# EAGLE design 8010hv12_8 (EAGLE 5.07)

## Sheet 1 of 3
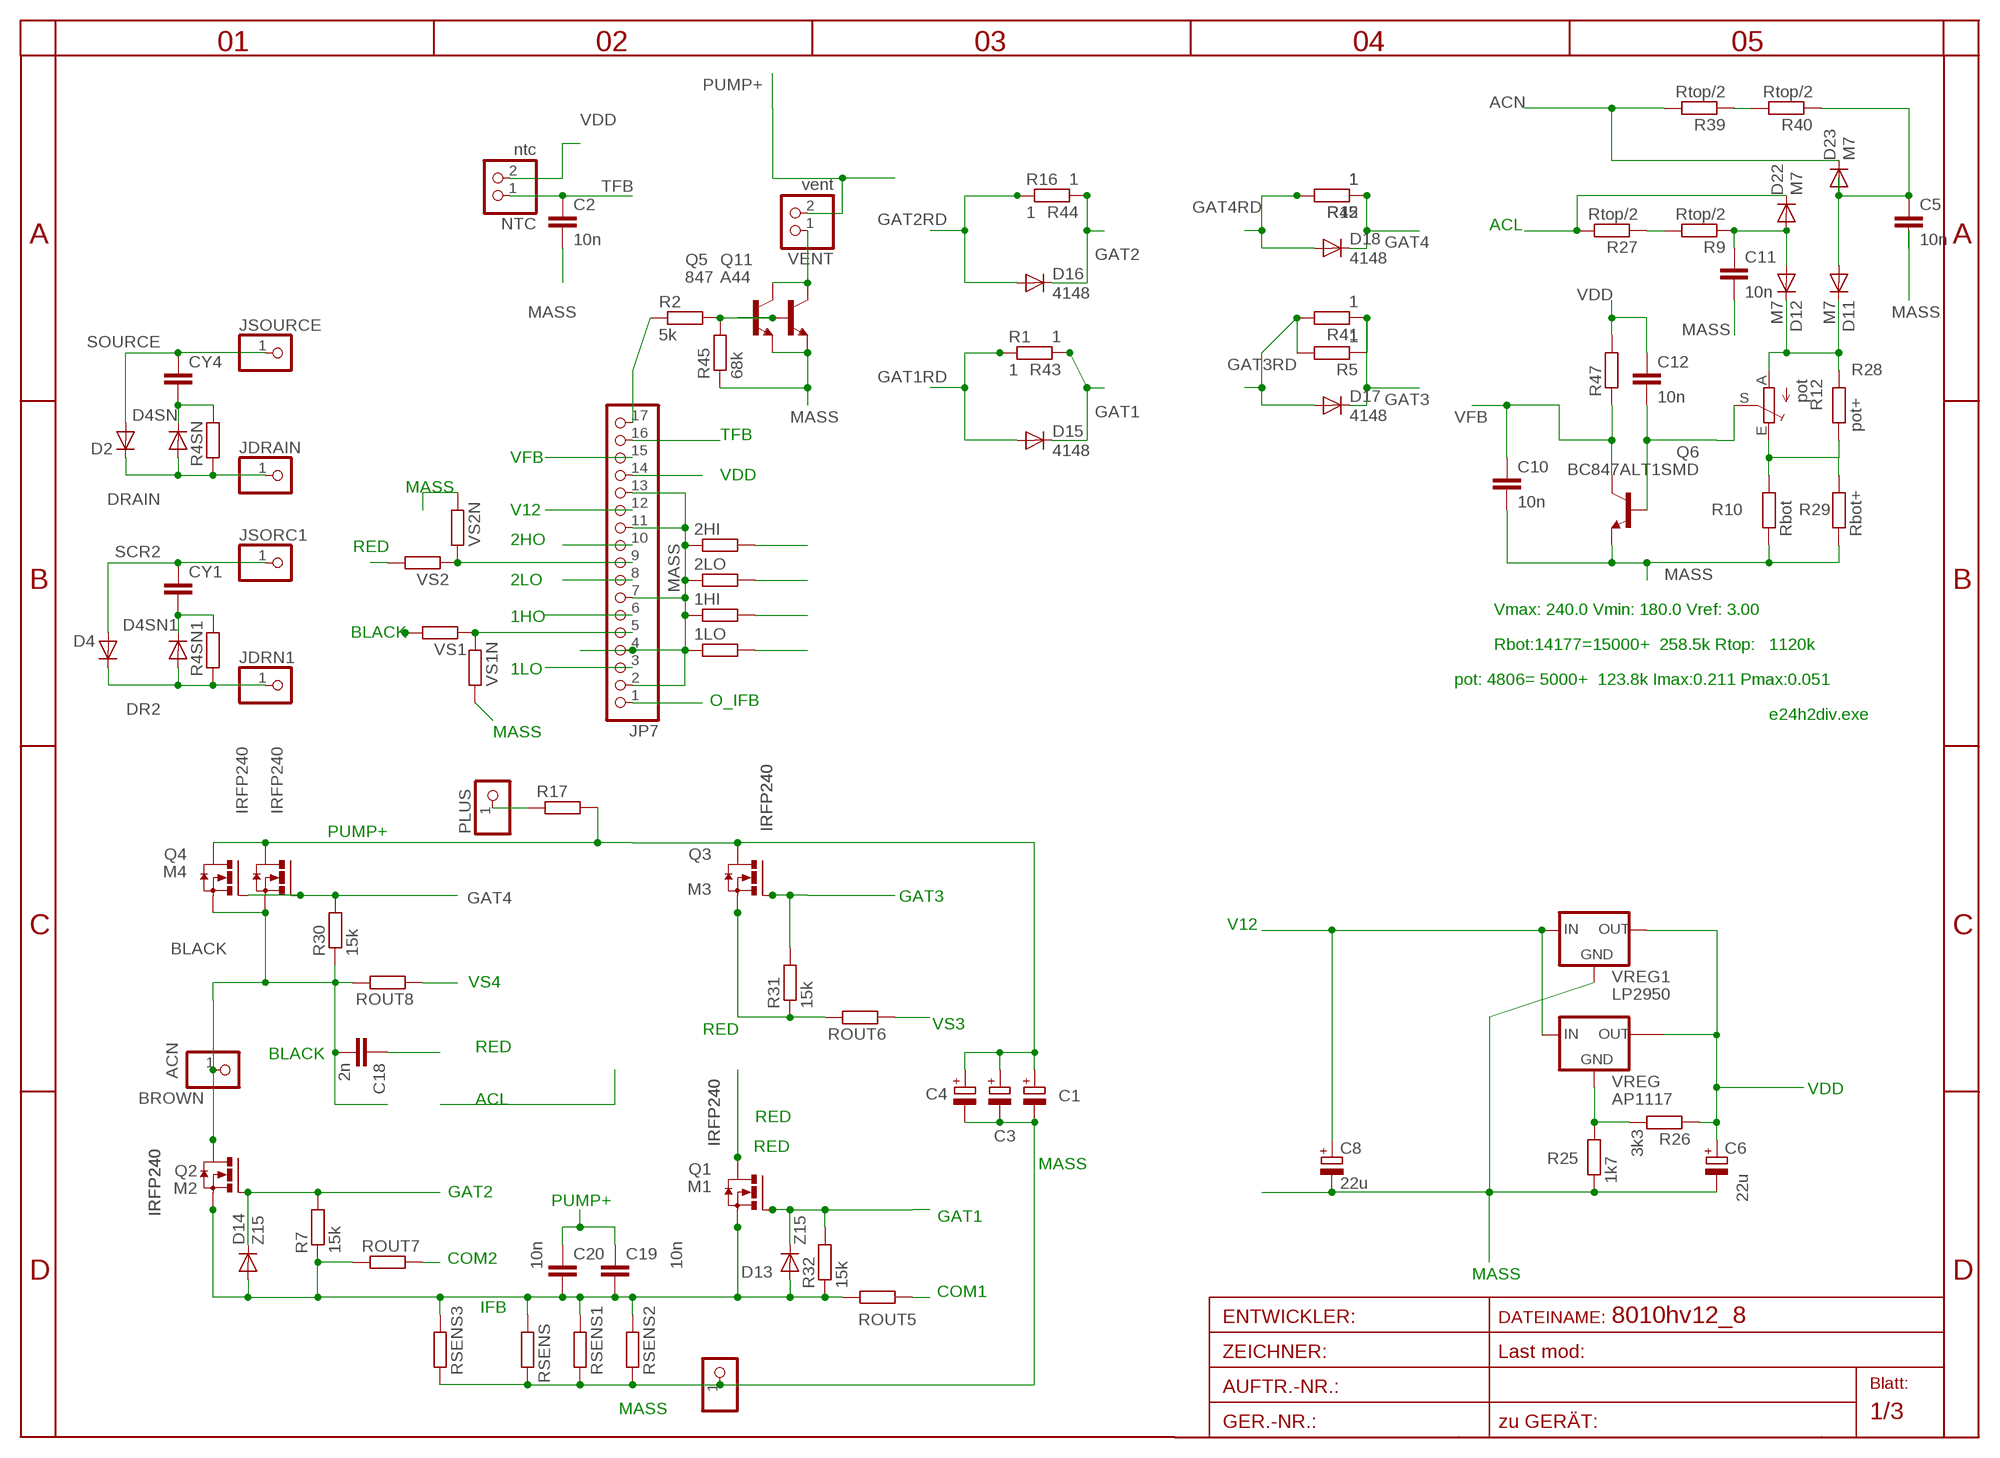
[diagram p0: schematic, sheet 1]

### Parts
1HI  R-EU_R0805  [R0805]
1LO  R-EU_R0805  [R0805]
2HI  R-EU_R0805  [R0805]
2LO  R-EU_R0805  [R0805]
BROWN  ACN  PINHD-1X12MM3  [1X2MM3]
C1  CPOL-EUE5-13  [E5-13]
C2  10n  C-EUC0805  [C0805]
C3  CPOL-EUE5-13  [E5-13]
C4  CPOL-EUE5-13  [E5-13]
C5  10n  C-EUC0805  [C0805]
C6  22u  CPOL-EUSMCA  [SMC_A]
C8  22u  CPOL-EUSMCA  [SMC_A]
C10  10n  C-EUC0805  [C0805]
C11  10n  C-EUC0805  [C0805]
C12  10n  C-EUC0805  [C0805]
C18  2n  C-EU050-024X044  [C050-024X044]
C19  10n  C-EU050-024X044  [C050-024X044]
C20  10n  C-EU050-024X044  [C050-024X044]
CY1  CXXC10B5  [XC10B5]
CY4  CXXC10B5  [XC10B5]
D2  DIODE-TO220V  [TO220ACS]
D4  DIODE-TO220V  [TO220ACS]
D4SN  DIODE-P1-10  [P1-10]
D4SN1  DIODE-P1-10  [P1-10]
D11  M7  DIODE-SMA-DO214  [SMA-DO214AC]
D12  M7  DIODE-SMA-DO214  [SMA-DO214AC]
D13  Z15  DIODE-MINIMELF  [MINIMELF]
D14  Z15  DIODE-MINIMELF  [MINIMELF]
D15  4148  DIODE-MINIMELF  [MINIMELF]
D16  4148  DIODE-MINIMELF  [MINIMELF]
D17  4148  DIODE-MINIMELF  [MINIMELF]
D18  4148  DIODE-MINIMELF  [MINIMELF]
D22  M7  DIODE-SMA-DO214  [SMA-DO214AC]
D23  M7  DIODE-SMA-DO214  [SMA-DO214AC]
JDRAIN  PINHD-1X11MM0  [1X1MM0]
JDRN1  PINHD-1X11MM0  [1X1MM0]
JP7  PINHD-1X17  [1X17]
JSORC1  PINHD-1X11MM0  [1X1MM0]
JSOURCE  PINHD-1X11MM0  [1X1MM0]
M1  IRFP240  [TO247BV]
M2  IRFP240  [TO247BV]
M3  IRFP240  [TO247BV]
M4  IRFP240  [TO247BV]
MINUS  PINHD-1X12MM3  [1X2MM3]
NTC  ntc  PINHD-1X2STR  [1X02]
PLUS  PINHD-1X12MM3  [1X2MM3]
Q1  IRFP240  [TO247BV]
Q2  IRFP240  [TO247BV]
Q3  IRFP240  [TO247BV]
Q4  IRFP240  [TO247BV]
Q5  847  SMBTA45HV  [SOT23HV]
Q6  BC847ALT1SMD  [SOT23]
Q11  A44  -NPN-TO92-EBC  [TO92-EBC]
R1  1  R-EU_R2512  [R2512]
R2  5k  R-EU_R0603  [R0603]
R4SN  R-EU_0207/10  [0207/10]
R4SN1  R-EU_0207/10  [0207/10]
R5  1  R-EU_R2512  [R2512]
R7  15k  R-EU_R1206  [R1206]
R9  Rtop/2  R-EU_R1206  [R1206]
R10  Rbot  R-EU_R0805  [R0805]
R12  pot  TRIM_EU-B64Y  [B64Y]
R15  1  R-EU_R2512  [R2512]
R16  1  R-EU_R2512  [R2512]
R17  R-EU_0309/10  [0309/10]
R25  1k7  R-EU_R0805  [R0805]
R26  3k3  R-EU_R0805  [R0805]
R27  Rtop/2  R-EU_R1206  [R1206]
R28  pot+  R-EU_R0805  [R0805]
R29  Rbot+  R-EU_R0805  [R0805]
R30  15k  R-EU_R1206  [R1206]
R31  15k  R-EU_R1206  [R1206]
R32  15k  R-EU_R1206  [R1206]
R39  Rtop/2  R-EU_R1206  [R1206]
R40  Rtop/2  R-EU_R1206  [R1206]
R41  1  R-EU_R1210  [R1210]
R42  1  R-EU_R1210  [R1210]
R43  1  R-EU_R1210  [R1210]
R44  1  R-EU_R1210  [R1210]
R45  68k  R-EU_R0805  [R0805]
R47  R-EU_R0805  [R0805]
ROUT5  R-EU_R2512  [R2512]
ROUT6  R-EU_R2512  [R2512]
ROUT7  R-EU_R2512  [R2512]
ROUT8  R-EU_R2512  [R2512]
RSENS  R-EU_WIRE  [WIRE]
RSENS1  R-EU_0309/10  [0309/10]
RSENS2  R-EU_0309/12  [0309/12]
RSENS3  R-EU_R2512  [R2512]
VENT  vent  PINHD-1X2STR  [1X02]
VREG  AP1117  [SOT223]
VREG1  LP2950  LP2950TO92-2MIL  [TO92-2MIL]
VS1  R-EU_R1005  [R1005]
VS1N  R-EU_R0805  [R0805]
VS2  R-EU_R1005  [R1005]
VS2N  R-EU_R0805  [R0805]

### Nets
1HO: 1HI.2 JP7.6 ; also sheet 3
1LO: 1LO.2 JP7.3 ; also sheet 3
2HO: 2HI.2 JP7.10 ; also sheet 3
2LO: 2LO.2 JP7.8 ; also sheet 3
ACL: D22.K(C) R27.2
ACN: D23.K(C) R39.2
BLACK: BROWN.1 C18.2 M2.D M4.S Q2.D Q4.S R30.1 ROUT8.2 VS1.2
COM1: ROUT5.1 ; also sheet 3
COM2: ROUT7.2 ; also sheet 3
DFG: JP7.9 VS2.1 VS2N.2
DR2: D4.C D4SN1.A JDRN1.1 R4SN1.1
DRAIN: D2.C D4SN.A JDRAIN.1 R4SN.1
GAT1: D13.C D15.C M1.G Q1.G R1.2 R32.2 R43.1
GAT1RD: D15.A R1.1 R43.2 ; also sheet 3
GAT2: D14.C D16.C M2.G Q2.G R7.2 R16.2 R44.1
GAT2RD: D16.A R16.1 R44.2 ; also sheet 3
GAT3: D17.C M3.G Q3.G R5.1 R31.2 R41.1
GAT3RD: D17.A R5.2 R41.2 ; also sheet 3
GAT4: D18.C M4.G Q4.G R15.1 R30.2 R42.1
GAT4RD: D18.A R15.2 R42.2 ; also sheet 3
IFB: C19.2 C20.2 D13.A D14.A M1.S M2.S Q1.S Q2.S R7.1 R32.1 ROUT5.2 ROUT7.1 RSENS1.1 RSENS2.1 RSENS3.1 RSENS.1 ; also sheet 3
IN+: PLUS.1 R17.1
JDH: JP7.5 VS1.1 VS1N.1
MASS: 1HI.1 1LO.1 2HI.1 2LO.1 C1.- C2.2 C3.- C4.- C5.2 C6.- C8.- C10.2 C11.2 JP7.2 JP7.4 JP7.7 JP7.11 JP7.13 MINUS.1 Q5.2(E) Q6.2(E) Q11.E R10.1 R25.1 R29.1 R45.1 RSENS1.2 RSENS2.2 RSENS3.2 RSENS.2 VREG1.2(GND) VS1N.2 VS2N.1 ; also sheet 2,3
N$1: Q5.3(C) Q11.C VENT.1
N$2: Q5.1(B) Q11.B R2.2 R45.2
N$3: JP7.17 R2.1
N$11: C11.1 D12.A D22.A R9.1
N$15: R39.1 R40.2
N$17: R25.2 R26.2 VREG.1(GND)
N$19: C5.1 D11.A D23.A R40.1
N$21: C12.2 Q6.1(B) R12.S
N$23: R9.2 R27.1
N$29: R10.2 R12.E R28.1 R29.2
N$30: D11.K(C) D12.K(C) R12.A R28.2
O_IFB: JP7.1 ; also sheet 3
PUMP+: C1.+ C3.+ C4.+ C19.1 C20.1 M3.D M4.D Q3.D Q4.D R17.2 VENT.2 ; also sheet 2
RED: C18.1 M1.D M3.S Q1.D Q3.S R31.1 ROUT6.2 VS2.2
SCR2: CY1.1 D4.A JSORC1.1
SNUB1: CY1.2 D4SN1.C R4SN1.2
SNUB2: CY4.2 D4SN.C R4SN.2
SOURCE: CY4.1 D2.A JSOURCE.1
TFB: C2.1 JP7.16 NTC.1
V12: C8.+ JP7.12 VREG1.3(IN) VREG.3(IN) ; also sheet 2,3
VDD: C6.+ C12.1 JP7.14 NTC.2 R26.1 R47.2 VREG1.1(OUT) VREG.4(TAB) ; also sheet 3
VFB: C10.1 JP7.15 Q6.3(C) R47.1
VS3: ROUT6.1 ; also sheet 3
VS4: ROUT8.1 ; also sheet 3
Unconnected: VREG.2(OUT)

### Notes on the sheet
- Vmax: 240.0 Vmin: 180.0 Vref: 3.00
- Rbot:14177=15000+  258.5k Rtop:   1120k
- pot: 4806= 5000+  123.8k Imax:0.211 Pmax:0.051
- e24h2div.exe

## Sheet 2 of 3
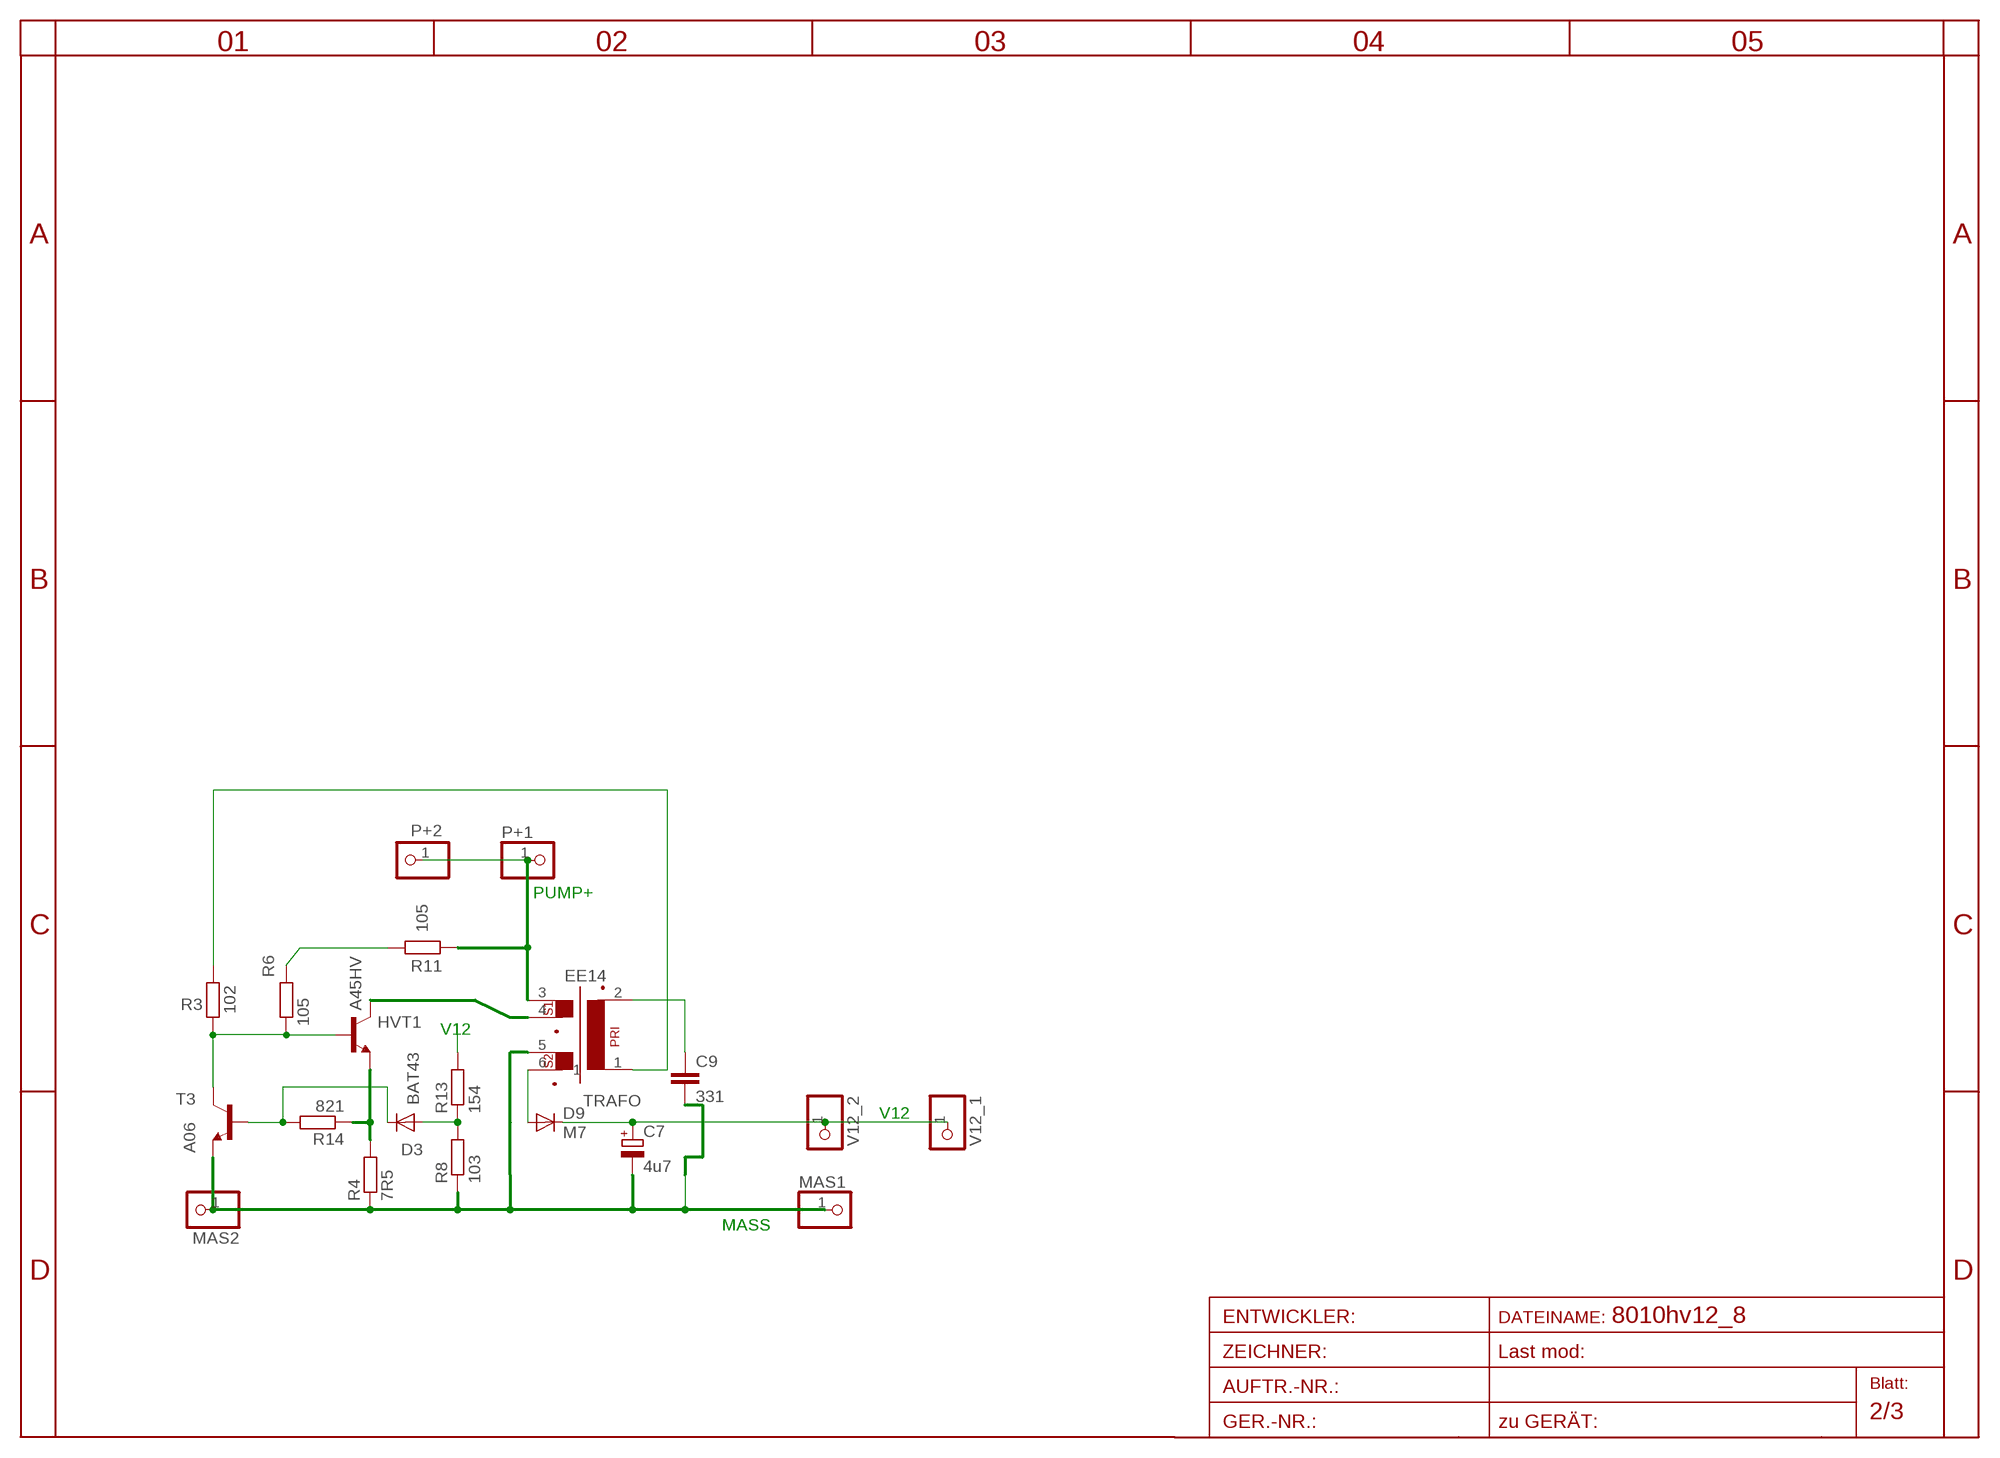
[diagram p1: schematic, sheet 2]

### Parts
C7  4u7  CPOL-EUSMCA  [SMC_A]
C9  331  C-EUC0805  [C0805]
D3  BAT43  DIODE-MINIMELF  [MINIMELF]
D9  M7  DIODE-SMA-DO214  [SMA-DO214AC]
HVT1  A45HV  SMBTA45HV  [SOT23HV]
MAS1  PINHD-1X11X0.4  [1X01]
MAS2  PINHD-1X11X0.4  [1X01]
P+1  PINHD-1X11X0.4  [1X01]
P+2  PINHD-1X11X0.4  [1X01]
R3  102  R-EU_R0805  [R0805]
R4  7R5  R-EU_R0805  [R0805]
R6  105  R-EU_R1206  [R1206]
R8  103  R-EU_R0805  [R0805]
R11  105  R-EU_R1206  [R1206]
R13  154  R-EU_R0805  [R0805]
R14  821  R-EU_R0805  [R0805]
T3  A06  BC848  [SOT23]
TRAFO  EE14  EE14EE14  [EE14]
V12_1  PINHD-1X11X0.4  [1X01]
V12_2  PINHD-1X11X0.4  [1X01]

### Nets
A: D9.A TRAFO.6
B1C2: HVT1.1(B) R3.1 R6.1 T3.C
BT1: D3.C R14.2 T3.B
C1: HVT1.3(C) TRAFO.4
EB: HVT1.2(E) R4.2 R14.1
MASS: C7.- C9.2 MAS1.1 MAS2.1 R4.1 R8.1 T3.E TRAFO.5 ; also sheet 1,3
N$6: R3.2 TRAFO.1
N$7: C9.1 TRAFO.2
N$8: R6.2 R11.2
N$10: D3.A R8.2 R13.1
PUMP+: P+1.1 P+2.1 R11.1 TRAFO.3 ; also sheet 1
V12: C7.+ D9.K(C) R13.2 V12_1.1 V12_2.1 ; also sheet 1,3

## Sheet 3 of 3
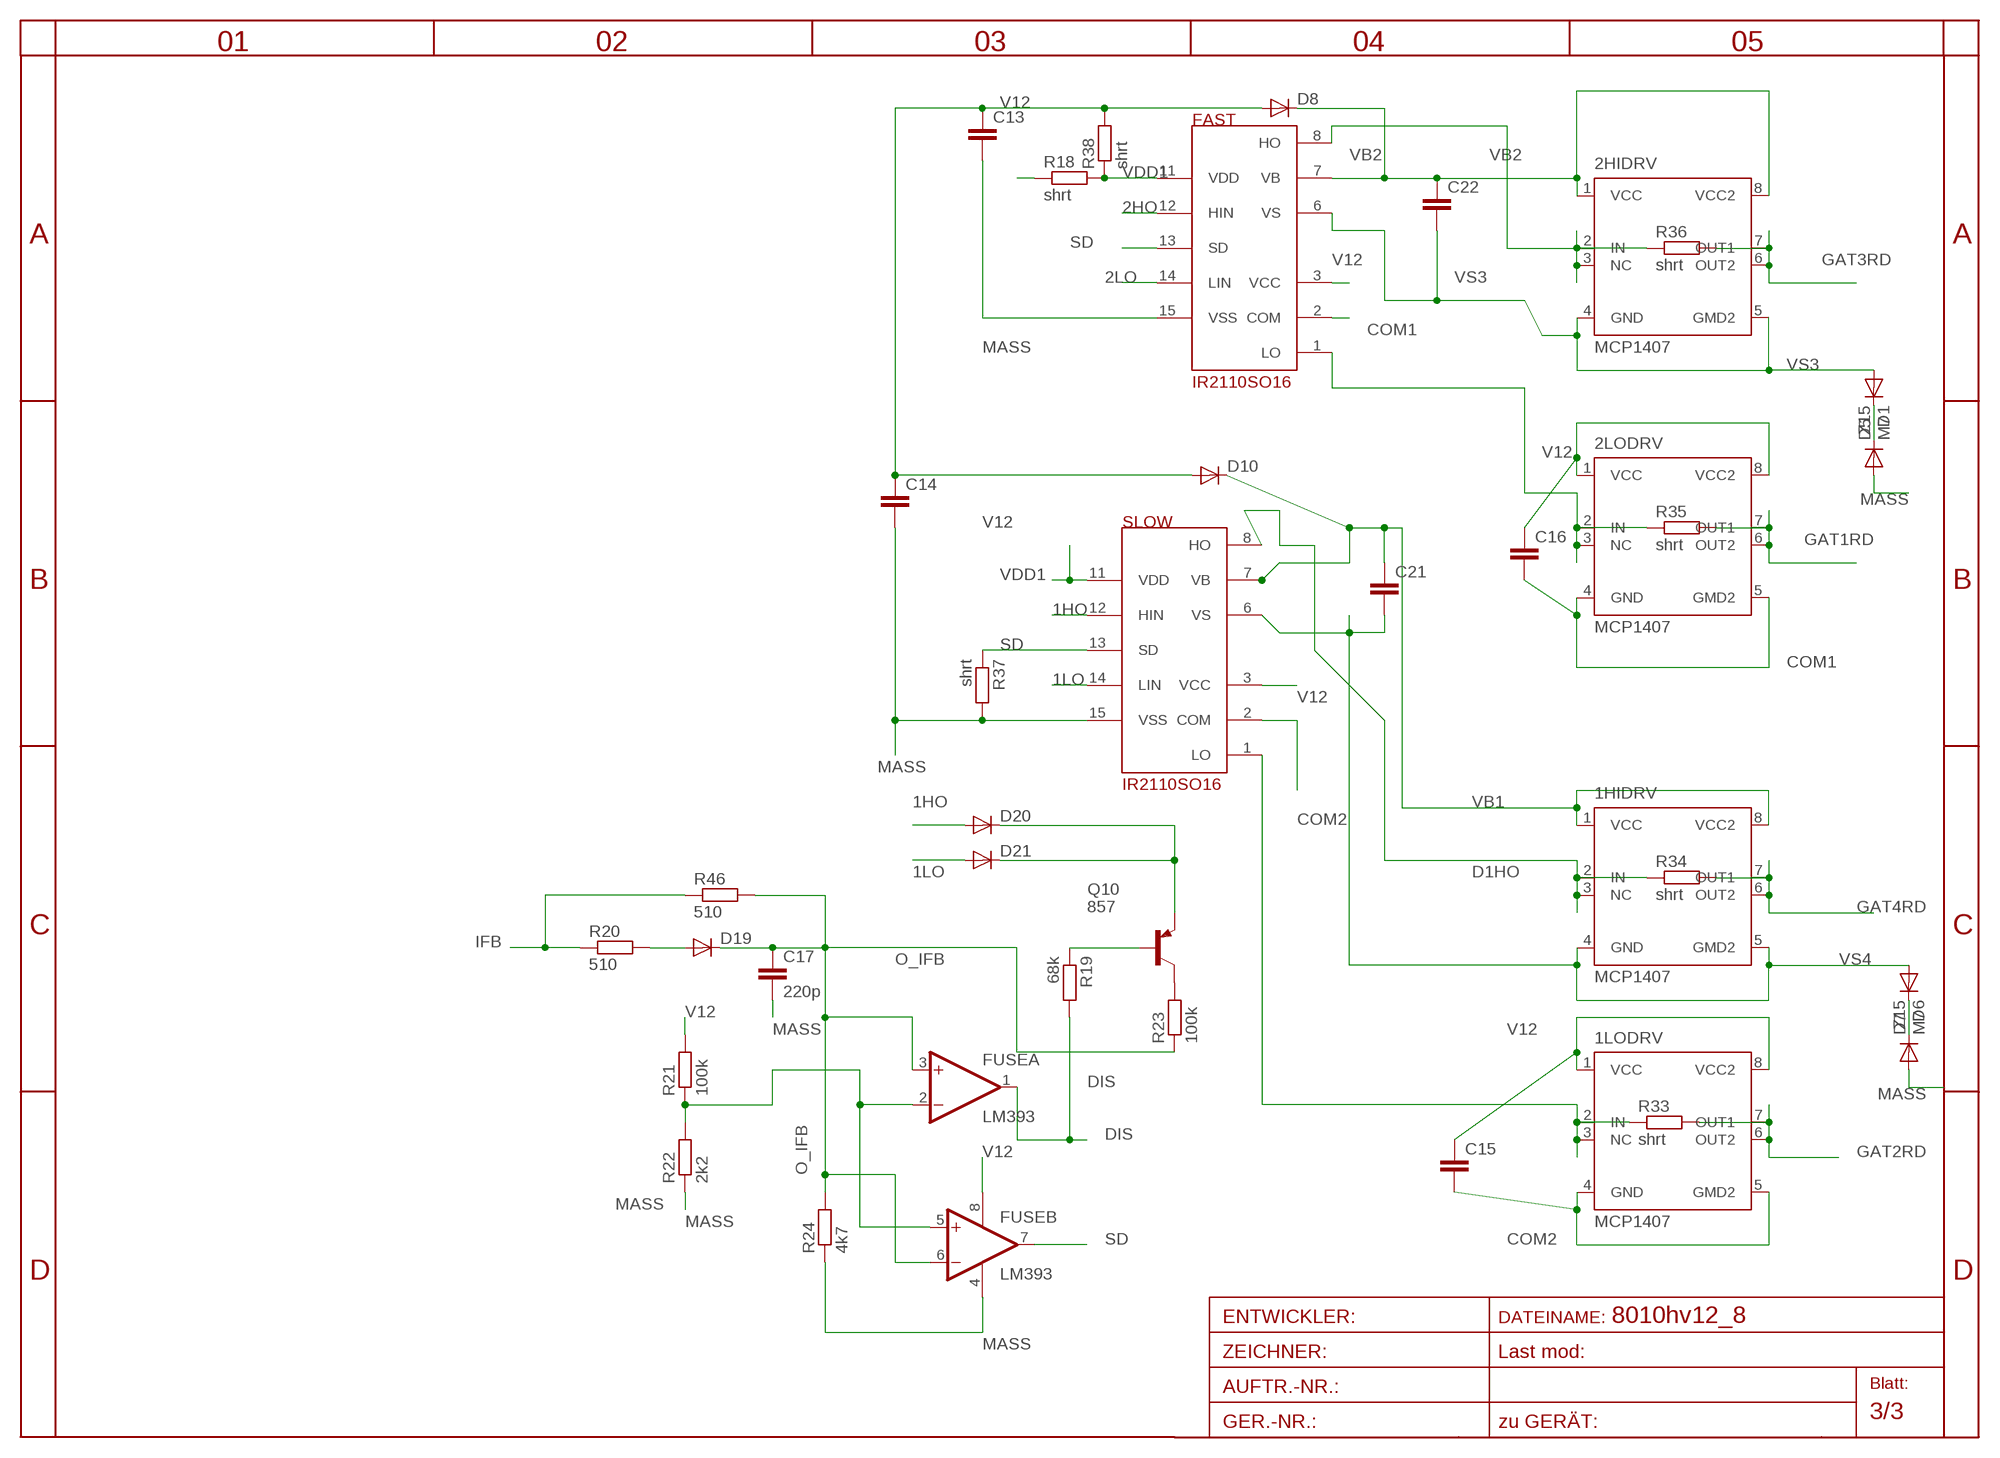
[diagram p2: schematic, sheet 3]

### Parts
1HIDRV  MCP1407  [SO-08M]
1LODRV  MCP1407  [SO-08M]
2HIDRV  MCP1407  [SO-08M]
2LODRV  MCP1407  [SO-08M]
C13  C-EUC1206  [C1206]
C14  C-EUC1206  [C1206]
C15  C-EUC1206  [C1206]
C16  C-EUC1206  [C1206]
C17  220p  C-EUC0805  [C0805]
C21  C-EUC1206  [C1206]
C22  C-EUC1206  [C1206]
D1  Z15  DIODE-MINIMELF  [MINIMELF]
D5  M7  DIODE-SMA-DO214  [SMA-DO214AC]
D6  Z15  DIODE-MINIMELF  [MINIMELF]
D7  M7  DIODE-SMA-DO214  [SMA-DO214AC]
D8  DIODE-SMA-DO214  [SMA-DO214AC]
D10  DIODE-SMA-DO214  [SMA-DO214AC]
D19  DIODE-SOT23  [SOT23]
D20  DIODE-SOT23  [SOT23]
D21  DIODE-SOT23  [SOT23]
FAST  IR2110SO16  [SO16DW]
FUSE  LM393  LM358D  [SO08]
Q10  857  BC857ALT1SMD  [SOT23-BEC]
R18  shrt  R-EU_R0402  [R0402]
R19  68k  R-EU_R0805  [R0805]
R20  510  R-EU_R0805  [R0805]
R21  100k  R-EU_R0805  [R0805]
R22  2k2  R-EU_R0805  [R0805]
R23  100k  R-EU_R0805  [R0805]
R24  4k7  R-EU_R0805  [R0805]
R33  shrt  R-EU_R1206  [R1206]
R34  shrt  R-EU_R1206  [R1206]
R35  shrt  R-EU_R1206  [R1206]
R36  shrt  R-EU_R1206  [R1206]
R37  shrt  R-EU_R0805  [R0805]
R38  shrt  R-EU_0204/5  [0204/5]
R46  510  R-EU_R0805  [R0805]
SLOW  IR2110SO16  [SO16DW]

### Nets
1HO: D20.1(A) SLOW.12(HIN) ; also sheet 1
1LO: D21.1(A) SLOW.14(LIN) ; also sheet 1
2HO: FAST.12(HIN) ; also sheet 1
2LO: FAST.14(LIN) ; also sheet 1
COM1: 2LODRV.4(GND) 2LODRV.5(GMD2) C16.2 FAST.2(COM) ; also sheet 1
COM2: 1LODRV.4(GND) 1LODRV.5(GMD2) C15.2 SLOW.2(COM) ; also sheet 1
D1HO: 1HIDRV.2(IN) 1HIDRV.3(NC) R34.1 SLOW.8(HO)
D1LO: 1LODRV.2(IN) 1LODRV.3(NC) R33.1 SLOW.1(LO)
DIS: FUSE.1(A:OUT) R19.2
GAT1RD: 2LODRV.6(OUT2) 2LODRV.7(OUT1) R35.2 ; also sheet 1
GAT2RD: 1LODRV.6(OUT2) 1LODRV.7(OUT1) R33.2 ; also sheet 1
GAT3RD: 2HIDRV.6(OUT2) 2HIDRV.7(OUT1) R36.2 ; also sheet 1
GAT4RD: 1HIDRV.6(OUT2) 1HIDRV.7(OUT1) R34.2 ; also sheet 1
IFB: R20.1 R46.1 ; also sheet 1
MASS: C13.2 C14.2 C17.2 D5.A D7.A FAST.15(VSS) FUSE.4(P:V-) R22.1 R24.1 R37.2 SLOW.15(VSS) ; also sheet 1,2
N$9: FUSE.2(A:-IN) FUSE.5(B:+IN) R21.1 R22.2
N$12: 2HIDRV.2(IN) 2HIDRV.3(NC) FAST.8(HO) R36.1
N$14: D19.1(A) R20.2
N$16: 2LODRV.2(IN) 2LODRV.3(NC) FAST.1(LO) R35.1
N$18: D20.3(C) D21.3(C) Q10.E
N$20: D1.C D5.K(C)
N$24: D6.C D7.K(C)
N$25: Q10.B R19.1
N$26: Q10.C R23.2
O_IFB: C17.1 D19.3(C) FUSE.3(A:+IN) FUSE.6(B:-IN) R23.1 R24.2 R46.2 ; also sheet 1
SD: FAST.13(SD) FUSE.7(B:OUT) R37.1 SLOW.13(SD)
V12: 1LODRV.1(VCC) 1LODRV.8(VCC2) 2LODRV.1(VCC) 2LODRV.8(VCC2) C13.1 C14.1 C15.1 C16.1 D8.A D10.A FAST.3(VCC) FUSE.8(P:V+) R21.2 R38.2 SLOW.3(VCC) ; also sheet 1,2
VB1: 1HIDRV.1(VCC) 1HIDRV.8(VCC2) C21.1 D10.K(C) SLOW.7(VB)
VB2: 2HIDRV.1(VCC) 2HIDRV.8(VCC2) C22.1 D8.K(C) FAST.7(VB)
VDD: R18.1 ; also sheet 1
VDD1: FAST.11(VDD) R18.2 R38.1 SLOW.11(VDD)
VS3: 2HIDRV.4(GND) 2HIDRV.5(GMD2) C22.2 D1.A FAST.6(VS) ; also sheet 1
VS4: 1HIDRV.4(GND) 1HIDRV.5(GMD2) C21.2 D6.A SLOW.6(VS) ; also sheet 1

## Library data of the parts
1HI 1LO 2HI 2LO R1-R4 R4SN R4SN1 R5-R8 R11 R13-R17 R19-R24 R30-R32 R38 R45-R47 ROUT5-ROUT8 RSENS RSENS1-RSENS3 VS1 VS1N VS2 VS2N = rcl:R-EU_: RESISTOR, European symbol
1HIDRV 1LODRV 2HIDRV 2LODRV = microchip:MCP1407
BROWN JDRAIN JDRN1 JSORC1 JSOURCE MAS1 MAS2 MINUS P+1 P+2 PLUS V12_1 V12_2 = pinhead:PINHD-1X1: PIN HEADER
C1 C3 C4 C6-C8 = rcl:CPOL-EU: POLARIZED CAPACITOR, European symbol
C2 C5 C9-C22 = rcl:C-EU: CAPACITOR, European symbol
CY1 CY4 = rcl:CX: X CAPACITOR
D1-D4 D4SN D4SN1 D5-D23 = diode:DIODE-: DIODE
FAST SLOW = ir2112:IR2110
FUSE = linear:LM358: OP AMP also LM158; LM258; LM2904 Source: http://cache.national.com/ds/LM/LM158.pdf
HVT1 Q5 = transistor-npn:SMBTA45
JP7 = pinhead:PINHD-1X17: PIN HEADER
M1-M4 Q1-Q4 = transistor-power:IRFP240: HEXFET Power MosFet Source: http://www.irf.com/
NTC VENT = pinhead:PINHD-1X2: PIN HEADER
Q6 = transistor-npn:BC847*: NPN Transistor
Q10 = transistor-pnp:BC857*: PNP Transistror
Q11 = transistor-neu-to92:*-NPN-: NPN Transistror
R9 R10 R25-R29 R39-R44 = rcl-2:R-EU_: RESISTOR, European symbol
R12 = pot:TRIM_EU-: POTENTIOMETER
R18 R33-R37 = rcl(2):R-EU_: RESISTOR, European symbol
T3 = transistor:BC848: NPN TRANSISTOR
TRAFO = trafo:EE14
VREG = v-reg:AP1117
VREG1 = v-reg:LP2950?*: Source: http://cache.national.com/ds/LP/LP2950.pdf

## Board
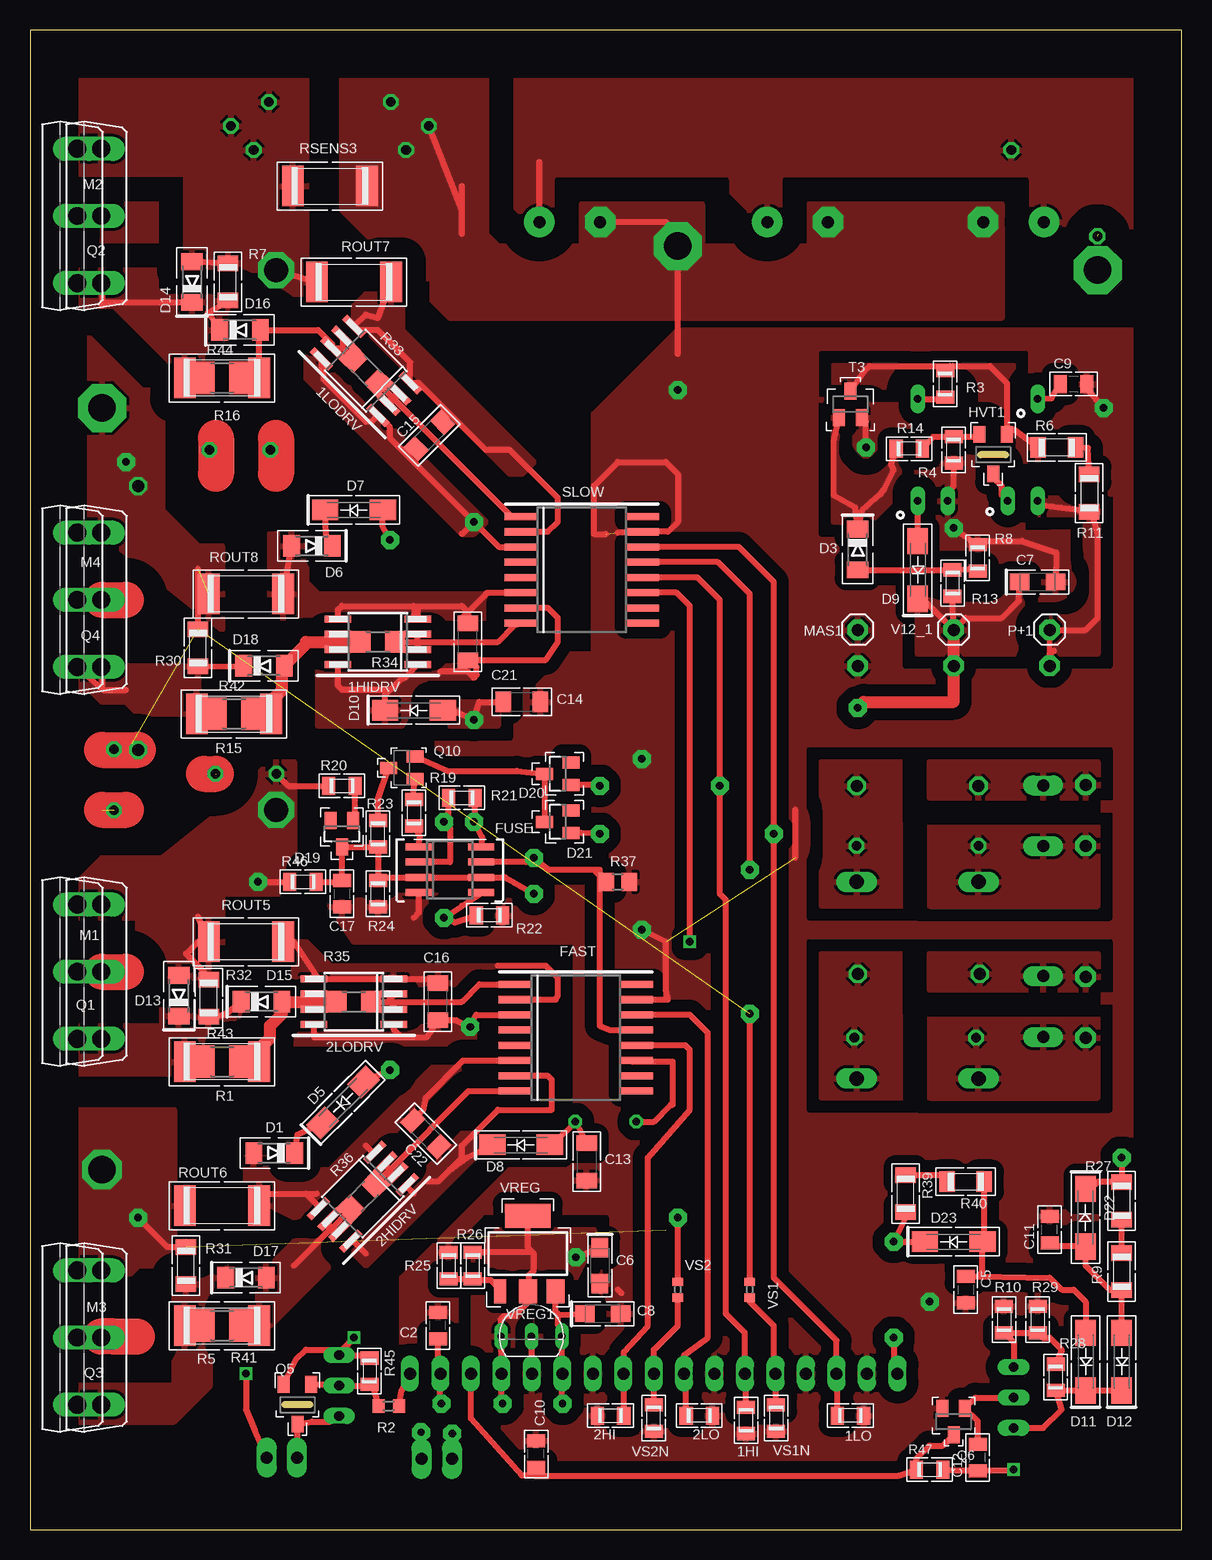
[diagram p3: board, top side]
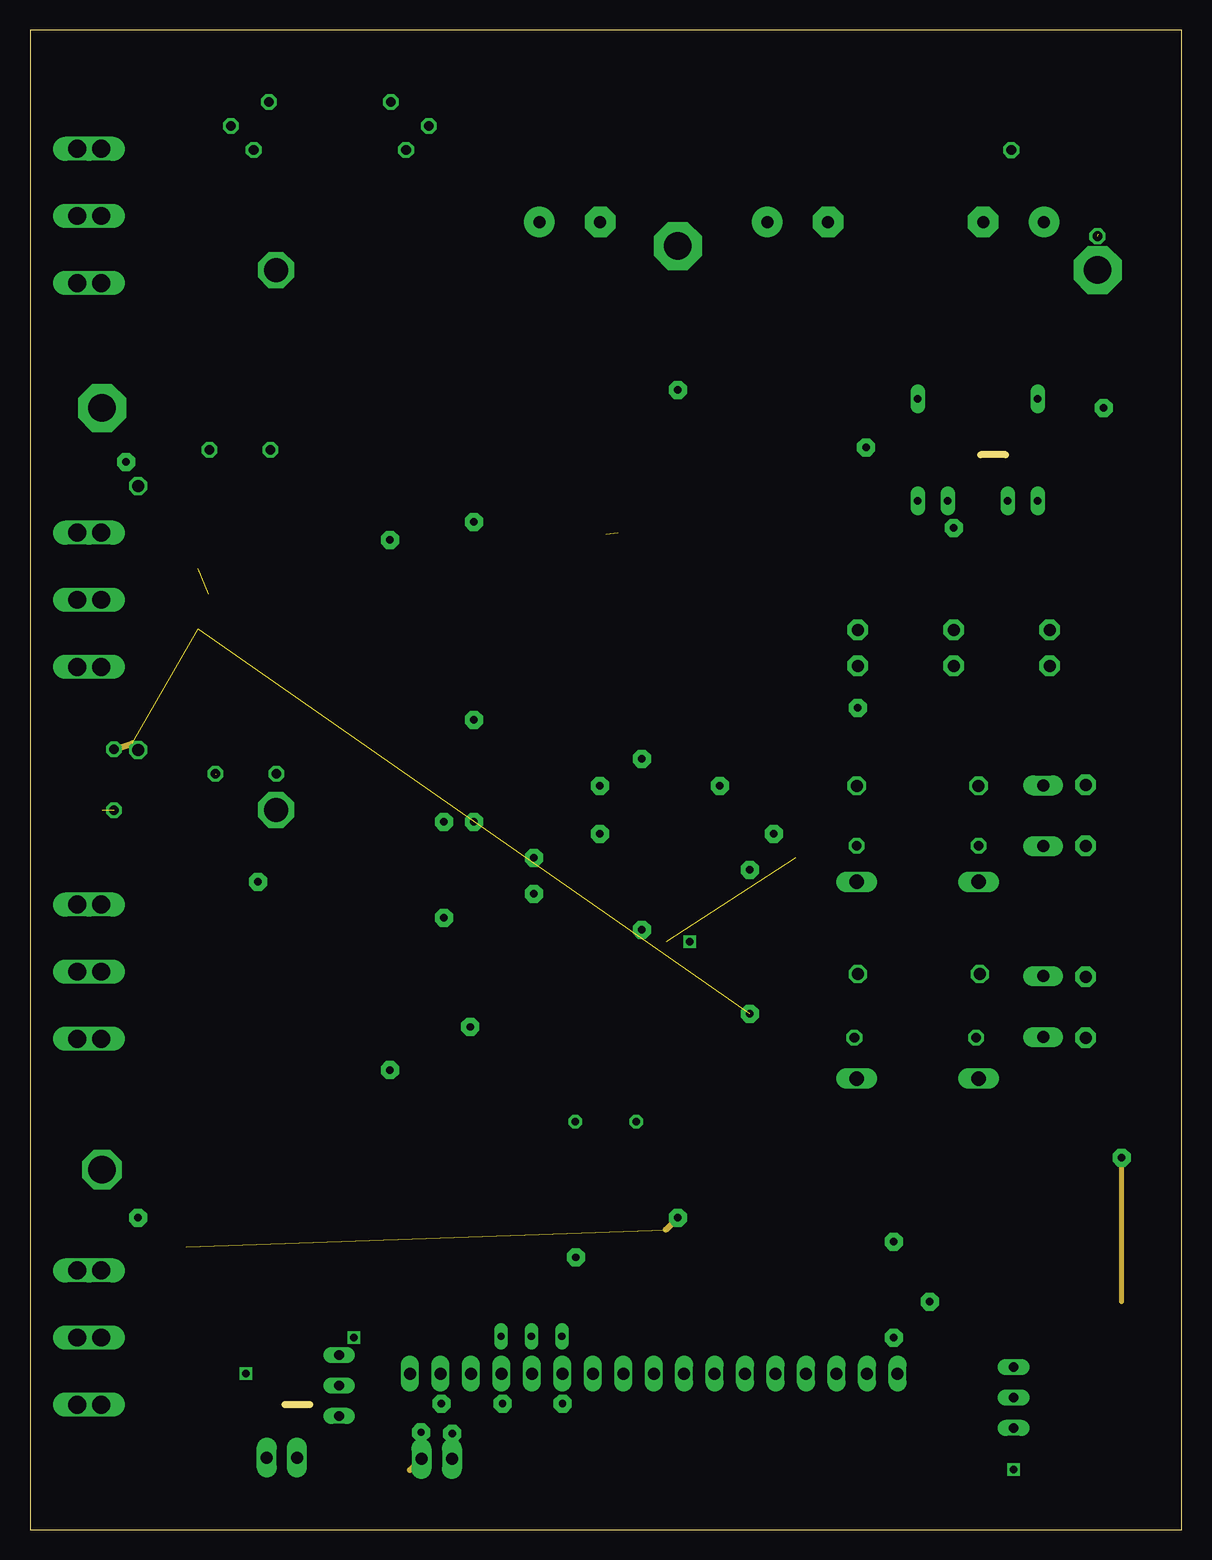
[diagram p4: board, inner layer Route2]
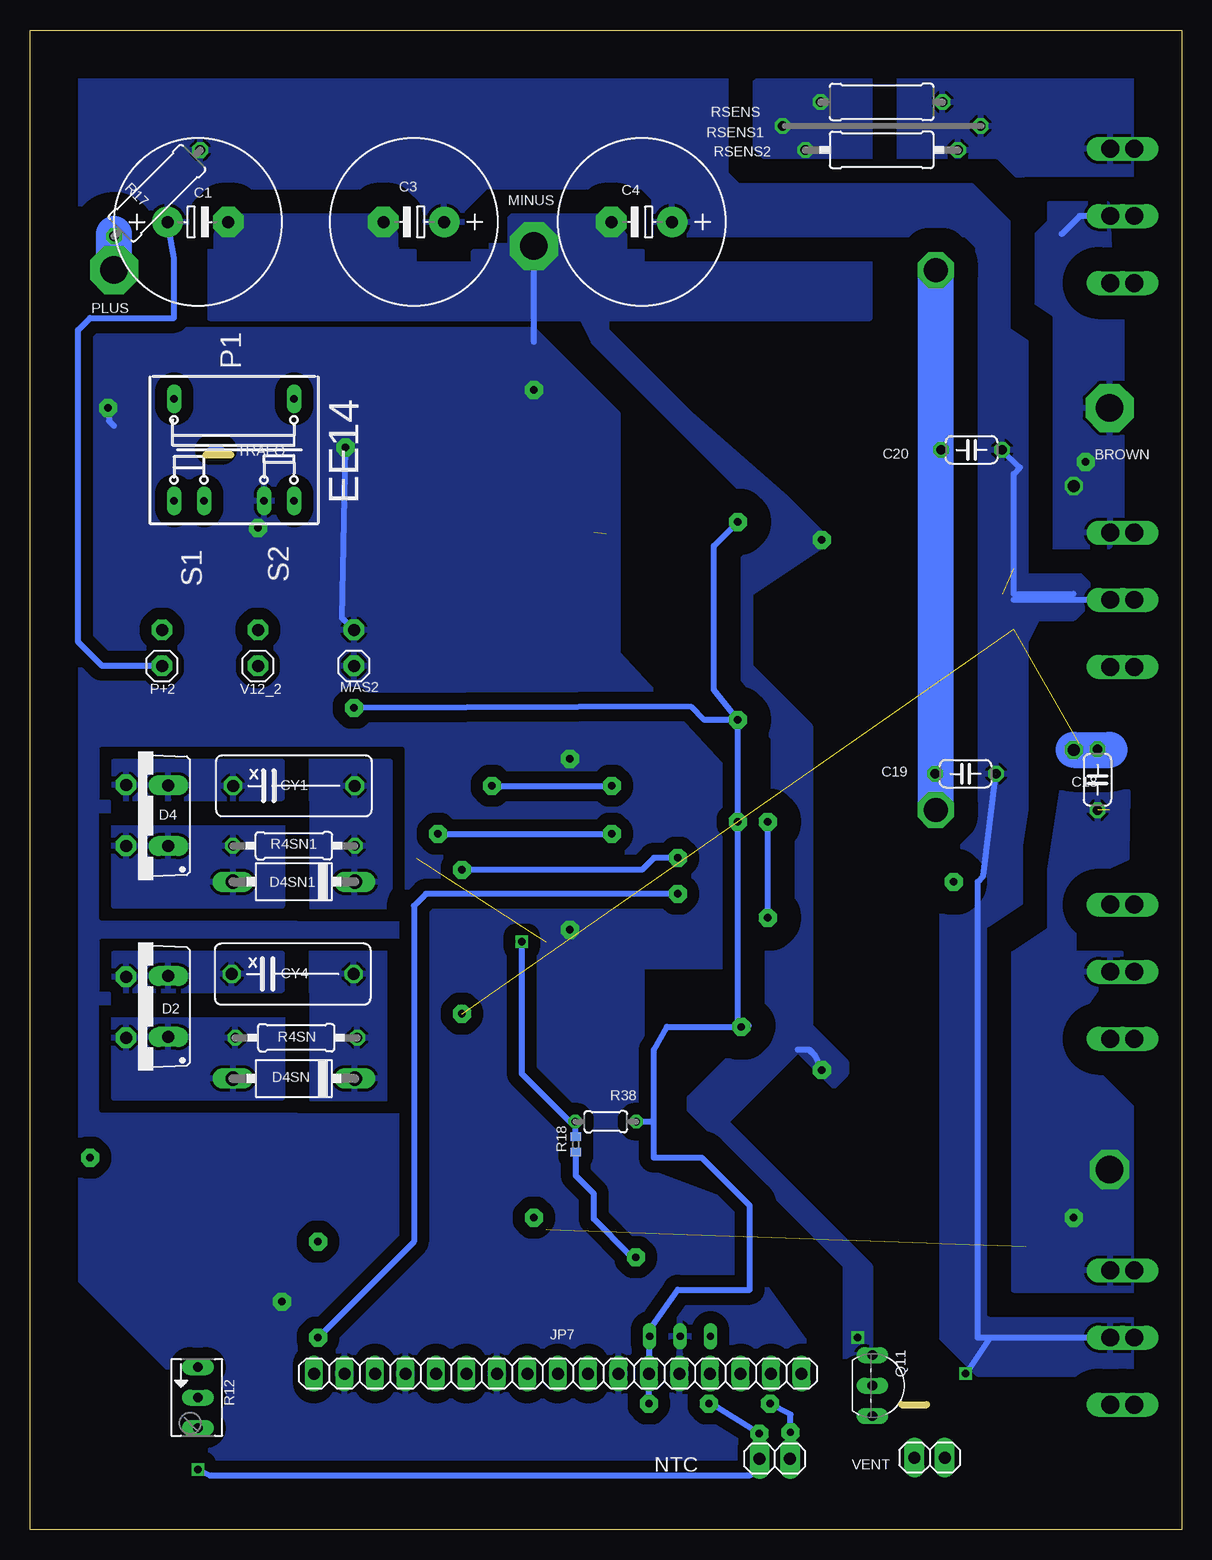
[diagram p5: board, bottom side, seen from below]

Size 96 x 125 mm. Coordinates in mm from the lower left corner, seen from the top.
Outline: 0,0 96,0 96,125 0,125 0,0
Copper layers (1*16): Top 0.035mm / dielectric 1.5mm / Bottom 0.035mm
Design rules "default *": minimum track width 10mil, minimum drill 20mil, track to track 8mil, track to pad 8mil, pad to pad 8mil, via to via 8mil, smd to smd 8mil, copper to edge 4mm, drill to drill 8mil, minimum pad ring 10mil, minimum via ring 8mil, stop-mask expansion 4mil, vias tented up to drill 0mil, thermal gap 10mil

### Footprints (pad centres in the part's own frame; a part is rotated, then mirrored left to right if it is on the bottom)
R0805 = smd 1.1 x 1.5: 1 -1.1,0; 2 1.1,0
SO-08M = smd 0.6 x 2.2: 1 -1.905,-3.33; 2 -0.635,-3.33; 3 0.635,-3.33; 4 1.905,-3.33; 5 1.905,3.33; 6 0.635,3.33; 7 -0.635,3.33; 8 -1.905,3.33
1X2MM3 = drill 2.3 pad 4 octagon: 1 0,0
E5-13 = drill 1 pad 2.54 round: + -2.54,0 | drill 1 pad 2.54 octagon: - 2.54,0
C0805 = smd 1.1 x 1.5: 1 -1.1,0; 2 1.1,0
SMC_A = smd 1.6 x 1.4: + -1.5,0; - 1.5,0
C1206 = smd 1.3 x 1.7: 1 -1.55,0; 2 1.55,0
C050-024X044 = drill 0.8 octagon: 1 -2.54,0; 2 2.54,0
XC10B5 = drill 1 octagon: 1 -5.08,0; 2 5.08,0
MINIMELF = smd 1.4 x 1.8: A 1.7,0; C -1.7,0
TO220ACS = drill 1 pad 1.676 long: A 2.54,-2.54; C -2.54,-2.54
P1-10 = drill 1.2 long: A 5.08,0; C -5.08,0
SMA-DO214AC = smd 2.2 x 1.7: A 2.4,0; K -2.4,0
SOT23 = smd 1 x 1.4: 1 -0.95,-1.1; 2 0.95,-1.1; 3 0,1.1
SO16DW = smd 0.6 x 2.7: 1 -4.445,-5.1; 2 -3.175,-5.1; 3 -1.905,-5.1; 4 -0.635,-5.1; 5 0.635,-5.1; 6 1.905,-5.1; 7 3.175,-5.1; 8 4.445,-5.1; 9 4.445,5.1; 10 3.175,5.1; 11 1.905,5.1; 12 0.635,5.1; 13 -0.635,5.1; 14 -1.905,5.1; 15 -3.175,5.1; 16 -4.445,5.1
SO08 = smd 0.6 x 2.2: 1 -1.905,-2.6; 2 -0.635,-2.6; 3 0.635,-2.6; 4 1.905,-2.6; 5 1.905,2.6; 6 0.635,2.6; 7 -0.635,2.6; 8 -1.905,2.6
SOT23HV = smd 1 x 1.4: 1 -1.15,-1.7; 2 1.15,-1.7; 3 0,1.6
1X1MM0 = drill 1 pad 1.676 octagon: 1 0,0
1X17 = drill 1 long: 1 -20.32,0; 2 -17.78,0; 3 -15.24,0; 4 -12.7,0; 5 -10.16,0; 6 -7.62,0; 7 -5.08,0; 8 -2.54,0; 9 0,0; 10 2.54,0; 11 5.08,0; 12 7.62,0; 13 10.16,0; 14 12.7,0; 15 15.24,0; 16 17.78,0; 17 20.32,0
TO247BV = drill 1.499 long: D 0,-2.921; G -5.588,-2.921; S 5.588,-2.921
1X01 = drill 1 pad 1.676 octagon: 1 0,0
1X02 = drill 1 pad 1.676 long: 1 -1.27,0; 2 1.27,0
SOT23-BEC = smd 1 x 1.4: B -0.95,-1.1; C 0,1.1; E 0.95,-1.1
TO92-EBC = drill 0.813 long: B 0,-1.27; C 2.54,-1.27; E -2.54,-1.27
R2512 = smd 1.8 x 3.4: 1 -3.1,0; 2 3.1,0
R0603 = smd 1 x 1.1: 1 -0.85,0; 2 0.85,0
0207/10 = drill 0.813 octagon: 1 -5.08,0; 2 5.08,0
R1206 = smd 1.3 x 1.7: 1 -1.55,0; 2 1.55,0
B64Y = drill 0.813 long: A 2.54,0; E -2.54,0; S 0,0
0309/10 = drill 0.813 octagon: 1 -5.08,0; 2 5.08,0
R0402 = smd 0.7 x 0.9: 1 -0.65,0; 2 0.65,0
R1206' = smd 1.6 x 1.803: 1 -1.422,0; 2 1.422,0
R0805' = smd 1.3 x 1.5: 1 -0.95,0; 2 0.95,0
0204/5 = drill 0.6 octagon: 1 -2.54,0; 2 2.54,0
R1210 = smd 1.6 x 2.7: 1 -1.4,0; 2 1.4,0
WIRE = drill 0.813 octagon: 1 -8.25,0; 2 8.25,0
0309/12 = drill 0.813 octagon: 1 -6.35,0; 2 6.35,0
SOT23' = smd 1 x 1.4: B -0.95,-1.1; C 0,1.1; E 0.95,-1.1
EE14 = drill 0.6 pad 1.2 long: 1 4.25,-5; 2 4.25,5; 3 -4.25,5; 4 -4.25,2.5; 5 -4.25,-2.5; 6 -4.25,-5
SOT223 = smd 1 x 2: 1 -2.3,-3.15 | smd 1.5 x 2: 2 0,-3.15; 3 2.3,-3.15 | smd 3.8 x 2: 4 0,3.15
TO92-2MIL = drill 0.6 pad 0.813 long: 1 -2.54,0; 2 0,0; 3 2.54,0
R1005 = smd 0.7 x 0.9: 1 -0.65,0; 2 0.65,0

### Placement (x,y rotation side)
1HI  59.7,9.1 90 top
1HIDRV  29,74 90 top
1LO  68.4,9.5 180 top
1LODRV  28,96.59 45 top
2HI  48.4,9.5 0 top
2HIDRV  27.75,27.75 135 top
2LO  55.8,9.5 180 top
2LODRV  27,44 90 top
BROWN  6,93.5 180 bottom
C1  82,109 0 bottom
C2  34,17 90 top
C3  64,109 180 bottom
C4  45,109 180 bottom
C5  78,20 270 top
C6  47.5,22 270 top
C7  84,79 0 top
C8  47.75,18 0 top
C9  87,95.5 0 top
C10  42.2,6.3 90 top
C11  85,25 90 top
C12  79,6 90 top
C13  46.4,30.65 270 top
C14  41,69 0 top
C15  33.3,91.2 45 top
C16  34,44 90 top
C17  26,53 270 top
C18  7,62.5 90 bottom
C19  18,63 180 bottom
C20  17.5,90 180 bottom
C21  36.5,74 90 top
C22  33,33 135 top
CY1  74,62 0 bottom
CY4  74.1,46.3 0 bottom
D1  20.36,31.38 180 top
D2  87,43.6 90 bottom
D3  69,81.7 270 top
D4  87,59.5 90 bottom
D4SN  74,37.6 180 bottom
D4SN1  74,54 180 bottom
D5  26.1,35.6 45 top
D6  23.5,82 180 top
D7  27,85 0 top
D8  40.93,32.07 0 top
D9  74,80 90 top
D10  32,68.3 0 top
D11  88,14 90 top
D12  91,14 90 top
D13  12.4,44.5 90 top
D14  13.5,104 90 top
D15  19.3,44 0 top
D16  17.5,100 0 top
D17  18,21 0 top
D18  19.5,72 0 top
D19  26,58 180 top
D20  44,63 90 top
D21  44,59 90 top
D22  88,26 270 top
D23  77,24 0 top
FAST  45.5,41 270 top
FUSE  35,55 270 top
HVT1  80.3,89.6 180 top
JDRAIN  88,41 270 top
JDRN1  88,57 0 top
JP7  52,13 0 bottom
JSORC1  88,62.08 0 top
JSOURCE  88,46.08 270 top
M1  3,46.5 90 top
M2  3,109.5 90 top
M3  3,16 90 top
M4  3,77.5 90 top
MAS1  69,75 270 top
MAS2  69,72 90 bottom
MINUS  54,107 270 bottom
NTC  33.9,5.9 180 bottom
P+1  85,75 270 top
P+2  85,72 90 bottom
PLUS  89,105 270 bottom
Q1  1,46.5 90 top
Q2  1,109.5 90 top
Q3  1,16 90 top
Q4  1,77.5 90 top
Q5  22.3,10.4 180 top
Q6  77,9 180 top
Q10  31,63.5 90 top
Q11  24.5,12 270 bottom
R1  16,39 180 top
R2  29.9,10.3 180 top
R3  76.3,95.5 270 top
R4  77,90 90 top
R4SN  73.8,41 0 bottom
R4SN1  74,57 0 bottom
R5  16,17 0 top
R6  85.6,90.2 0 top
R7  16.5,104 270 top
R8  79,81 270 top
R9  91,21.5 90 top
R10  81.2,17.5 270 top
R11  88.3,86.4 90 top
R12  82,11 270 bottom
R13  76.9,78.9 270 top
R14  73.3,90.1 180 top
R15  17,68 0 top
R16  16,96 180 top
R17  85.4,111.4 45 bottom
R18  50.5,32.1 90 bottom
R19  32,59.75 270 top
R20  26,62 0 top
R21  36,61 0 top
R22  38.3,51.2 180 top
R23  29,58 90 top
R24  29,53 90 top
R25  34.9,22 270 top
R26  36.9,22 270 top
R27  91,27.4 90 top
R28  85.5,12.7 270 top
R29  84,17.5 270 top
R30  14,73.5 270 top
R31  13,22 270 top
R32  14.9,44.3 270 top
R33  shrt  [R1206']  28,96.59 135 top
R34  shrt  [R1206']  29,74 180 top
R35  shrt  [R1206']  27,44 180 top
R36  shrt  [R1206']  27.75,27.75 225 top
R37  shrt  [R0805']  49,54 0 top
R38  48,34 0 bottom
R39  73,28 270 top
R40  78,29 180 top
R41  16,17 0 top
R42  17,68 0 top
R43  16,39 0 top
R44  16,96 0 top
R45  28.3,13.2 270 top
R46  22.75,54 0 top
R47  75,5 0 top
ROUT5  18,49 180 top
ROUT6  16,27 180 top
ROUT7  27,104 0 top
ROUT8  18,78 180 top
RSENS  25,117 180 bottom
RSENS1  25,119 180 bottom
RSENS2  25,115 180 bottom
RSENS3  25,112 0 top
SLOW  46,80 270 top
T3  A06  [SOT23']  68.4,93.8 0 top
TRAFO  79,90 90 bottom
V12_1  77,75 270 top
V12_2  77,72 90 bottom
VENT  21,6 0 bottom
VREG  41.5,23 0 top
VREG1  41.8,16.1 0 top
VS1  60,20 90 top
VS1N  62.2,9.3 270 top
VS2  54,20 90 top
VS2N  52,9.3 90 top

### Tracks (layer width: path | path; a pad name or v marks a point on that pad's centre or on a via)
1HO  (via drill 0.6 pad 1.5)
  Top 0.5: D20.1 46.95,62.05 v47.5,62 | 1HI.2 59.7,12.92 JP7.6 59.6,14.4 59.6,16.4 58,18 58,52.5 57.5,53 v57.5,62 57.5,73 57.5,77.5 56,79 55.63,79.36 SLOW.12
  Bottom 0.5: v57.5,62 v47.5,62
1LO  (via drill 0.6 pad 1.5)
  Top 0.5: D21.1 46,58.05 v47.5,58 | 1LO.2 67.3,12.94 JP7.3 67.24,15.76 62,21 v62,58 62,79 59.09,81.91 SLOW.14
  Bottom 0.5: v62,58 v47.5,58
2HO
  Top 0.5: 2HI.2 49.5,12.96 JP7.10 49.5,14.8 51.5,17 51.5,21 51.5,22 51.5,31 55,35 55,40 54.63,40.37 FAST.12
2LO
  Top 0.5: 2LO.2 54.7,12.84 JP7.8 54.54,14.54 56.5,16 56.5,41.41 55,42.91 FAST.14
A
  Top 0.5: D9.A TRAFO.6
ACL  (via drill 0.6 pad 1.5)
  Top 0.5: v91,31 R27.2 90.95,29 89,29 88.4,28.4 D22.K
  Route2 0.406: 91,19 v91,31
ACN  (via drill 0.6 pad 1.5)
  Top 0.5: R39.2 73,26 v72,24 73,24 D23.K
B1C2
  Top 0.5: R6.1 82.05,91.7 HVT1.1 81.45,95.55 80,97 76.9,97 | 76.7,97 R3.1 76.9,97 | T3.C 69.6,96.6 70,97 76.7,97 | 76.7,97 76.9,97
  pour Top (isolate 2): 82,92 82,97 67,97 67,94 80,94 80,92 83,89 85,89 85,91
BLACK  (via drill 0.6 pad 1.5, 1 pad 1.5)  (3 unrouted)
  Top 0.5: Q4.S M4.S | VS1.2 v60,43 | R30.1 14,80.1
  Route2 0.5: C18.2 8.54,65.54
  Bottom 0.5: M2.D 8.5,109.5 10,108
  other vias: 9,87 8,89
  pour Bottom (isolate 2, rank 3): 6.2,110.5 11,110.5 11,109 13,107 13,101 11,99 11,82 6,82 6,83 5,84 5,105 6,106
  pour Top (isolate 2, rank 3): 6.2,110.5 10.8,110.5 arc-41 11.4,100.5 11,100 11,85 14,82 16,82 16,75 6,83 5,84 5,105 6,106
BT1
  Top 0.5: T3.B 67,90.75 67,86.2 68.8,85.2 D3.C 69.4,85 70.9,86.3 71.2,86.7 72,88.3 71.8,88.8 R14.2
  pour Top (isolate 1.5, rank 2): 74,90 74,88 70,84 67,84 67,93 69,93 69,92 71,90
C1
  Top 0.5: HVT1.3 80.3,87.7 81,87 81,86.25 TRAFO.4
COM1
  Top 0.5: ROUT5.1 22,49 24,46 23.77,46 2LODRV.5 29.91,45.91 30,46 30.23,46 2LODRV.4 34.65,45.91 C16.2 | 39,47 43,47 44,46 44,44.5 43.83,44.17 FAST.2
  pour Top (isolate 1): 22,49 23,49 25,47 39,47 39,45 37,45 23,45 22,46 22,48
COM2
  Top 0.5: 35,93 38,90 40,90 44,86 44,84 43.17,83.17 SLOW.2 | 35,93 32.42,95.58 1LODRV.4 31.7,97.3 29,100 27.28,100 1LODRV.5 28,101.28 29,101 ROUT7.2 | C15.2 34.4,92.4 35,93
  pour Top (isolate 1): 31,103 31,100 42,89 41,88 40,88 27,101 27,102 28,103
D1HO
  Top 0.5: SLOW.8 40.4,75.4 39,74 32.4,74 32.4,73.87 1HIDRV.2 32.33,74 | 32.33,74 1HIDRV.3 | R34.1 32.33,74
D1LO
  Top 0.5: 30.12,94.46 29.84,94.75 R33.1 40.14,84.44 SLOW.1 | 1LODRV.3 30.59,94.46 30.12,94.46 | 1LODRV.2 30.12,94 30.12,94.46
DFG
  Top 0.5: VS2.1 54,17 52,15 JP7.9 VS2N.2
DIS
  Top 0.5: R19.2 32.5,57.8 FUSE.1
DR2
  pour Top (isolate 2, rank 2): 89,59 75,59 75,52 89,52
  pour Bottom (isolate 2, rank 2): 89,59 75,59 75,52 89,52
DRAIN
  pour Top (isolate 2, rank 2): 89,43 75,43 75,36 89,36
  pour Bottom (isolate 2, rank 2): 89,43 75,43 75,36 89,36
EB
  Top 0.5: R14.1 75.3,91.1 R4.2 78.95,91.1 HVT1.2
GAT1
  Top 0.5: R32.2 16.25,42.95 D15.C | Q1.G M1.G
  Top 1: R43.1 R1.2
  pour Top (isolate 2): 3,42 11,42 11,44 18,44 16,38 3,38
GAT1RD
  Top 0.5: 25,44 R35.2 | 25,44 24.3,44 2LODRV.7 | 2LODRV.6 24.36,44.63 25,44
  Top 1: R35.2 25,44 D15.A 21,43 20,42 20,41 19.1,40.1 R1.1 R43.2
GAT2
  Top 0.5: R7.2 14.85,101.45 D16.C | D14.C 6.3,102.3 6,102 6,104 6.07,104 M2.G | R44.1 R16.2
  pour Top (isolate 2, rank 2): 2,105 11,105 18,103 18,97 12,97 7,102 2,102
GAT2RD
  Top 0.5: 26.09,98.49 R33.2 | 26.09,98.49 1LODRV.7 25.2,98.8 24,100 D16.A 19.1,100 R16.1 R44.2 | 26.09,98.49 1LODRV.6
GAT3
  pour Top (isolate 2, rank 3): 3,12 3,9 12,9 15,12 15,18 17,22 12,20 12,12
GAT3RD
  Top 0.5: 22,22 24.95,24.95 | 24.95,24.95 2HIDRV.6 | 24.95,24.95 25,25 | 25,25 R36.2 | 2HIDRV.7 25.05,24.95 25,25 | R41.2 R5.2
  pour Top (isolate 1.5, rank 3): 22,24 29,28 26,23 20,17 19,17 19,22 20,22
GAT4
  Top 0.5: Q4.G 6.07,70 | 6.07,70 8,70 | R30.2 14.75,71.95 D18.C | 6.07,70 6.07,71.76 M4.G | R15.1 R42.1
  pour Top (isolate 1.5): 2.9,72.5 6.9,72.5 8,72 14,72 14,68 9,68 8,69 6,69 5,70 3,70
GAT4RD
  Top 0.5: R42.2 R15.2 | R34.2 26.3,74 1HIDRV.7 | 1HIDRV.6 25.67,74.33 26,74
  Top 1: R15.2 20.1,69.1 21,70 21,71.8 D18.A 23,73.8 23,74 26,74 R34.2
IFB  (via drill 0.6 pad 1.5, 2 pad 1.5)
  Top 0.5: D14.A 14.35,105.7 R7.1 | 14,51.1 ROUT5.2 14,49 13,48 14.5,46.5 R32.1 | v20.5,105 ROUT7.1 | 20.5,91 20.5,90.46 C20.2 | R20.1 21.54,62 C19.2 | v19,54 R46.1
  Top 3: 20.5,91 20.5,88
  Bottom 0.5: v20.5,105 20.5,90.46 C20.2
  Bottom 3: v20.5,60 v20.5,105
  pour Top (isolate 2, rank 2): 3,51 3,54 4,54 6,56 11,56 16,60 20,64 22,64 22,53 16,53 16,46 9,46 9,51
  pour Top (isolate 2): 3,121 23,121 23,103 22,103 19,105 13,105 13,113 4,113 3,114
  pour Bottom (isolate 2, rank 4): 3,121 24,121 24,113 4,113 3,114
IN+  (1 unrouted)
  Bottom 3: PLUS.1 89,108
JDH
  Top 0.5: VS1.1 60,19 62,17 62,13.16 JP7.5 62.2,12.96 VS1N.1
MASS  (via drill 0.6, 0.6 pad 1.5)  (2 unrouted)
  Top 0.5: C7.- 85.55,81.45 82.7,82.4 79.8,82.4 R8.1 78.9,82.1 v77,83.5 | C9.2 88.1,95.1 v89.5,93.5 | TRAFO.5 76.5,86.5 77,87 R4.1 | v69.7,90.2 69.7,92.35 T3.E | 36,110 36,112 | 47,109 C4.- 53,109 54,108 54,98 | 36,108 36,110 | 36,110 RSENS.2 | 49.3,19.7 49,20 | FUSE.4 32.4,51.4 32,51 | FAST.15 53.17,44.17 53,45 53,49 v51,50 | D7.A 29.4,83.6 v30,82.5 | SLOW.15 53.17,83.17 54,84 54,88 53,89 49,89 47,87 47,83 48,83 | D5.A 28.1,37.5 v30,38.3 | JP7.13 41.84,16.06 VREG1.2 | v27,16 26.73,15.73 | Q5.2 22.15,14.15 23,15 26,15 v27,16 | v27,16 26.77,15.77 Q11.E 28.06,14.54 R45.1 | 63.8,56 63.8,60 | 50,83.1 49,83.1
  Bottom 0.5: v69.7,90.2 70,76 MAS1.1 | v89.5,93.5 89.4,92.4 89,92 | v77,83.5 77,83 | v30,38.3 30.57,39.5 | 30.57,39.5 31,40 | 54,99 MINUS.1 | 32,40 31.06,40 30.57,39.5
  other vias: 51,64.25 54,95 75,19
  pour Bottom (isolate 2): 90,97 90,73 67,73 67,97
  pour Top (isolate 2, rank 5): 90,97 90,73 67,73 67,97
  pour Bottom (isolate 1, rank 4): 35,60 47,73 47,93 54,100 93,100 93,22 83,12 83,4 23,4 36,22 37,27 45,30 45,47 34,47
  pour Top (isolate 1, rank 4): 47,93 54,100 94,100 92,23 82,4 31,4 31,21 40,30 45,30 45,34 45.5,34 45.5,49 27,49 25,52 36,69 37,70 42,70 45,73 47,73
  pour Bottom (isolate 2, rank 3, no thermals): 26,101 26,121 35,121 38,119 38,108 39,107 45.8,107 48,110 56,110 56,107 65,107 65,110 80,110 81,109 81,101
  pour Top (isolate 2, rank 2, no thermals): 26,121 38,121 38,108 39,107 46,107 46,110.5 56,110.5 56,107 65,107 65,110.5 81,110.5 81,101 35,101 26,110
  pour Bottom (isolate 2): 26,22 26,14 28,14 28,22 41,35 41,36 37,40 37,46 34,49 34,66 38,70 38,81 37,82 36,86 49,99 50,101 48,103 48,100 41,93 33,86 30,83 30,82 36,78 36,72 31,67 31,42 28,39 28,38 29,37 32,40 38,34
N$1
  Top 0.5: VENT.1 22.3,7.03 Q5.3 23.5,9 25,9 25.46,9.46 Q11.C
N$2
  Top 0.5: Q5.1 26.67,12.1 Q11.B 28.55,12 | 28.55,12 R2.2 | 28.55,12 28.4,12 R45.2
N$3
  Top 0.5: R2.1 30.98,11.6 JP7.17
N$4
  Bottom 0.5: 80,90 81,90
N$6
  Top 0.5: TRAFO.1 75.95,94.25 R3.2
N$7
  Top 0.5: C9.1 85.15,94.3 TRAFO.2
N$8
  Top 0.5: R11.2 88.2,90.15 R6.2
N$9  (via drill 0.6 pad 1.5)
  Top 0.5: R21.1 34.9,59.1 34.8,59 v34.5,59 35,58.5 35,55.63 FUSE.2 | FUSE.5 37.51,53 36,52 v34.5,51 35.4,50.6 R22.2
  Bottom 0.5: v34.5,51 v34.5,59
N$10
  Top 0.5: R8.2 78.8,80.1 R13.1 D3.A
N$11
  Top 0.5: D12.A R9.1 90.05,19.95 88,22 D22.A 85.5,23.6 C11.1
N$12
  Top 0.5: FAST.8 36.55,36.55 30,30 | 29.66,29.66 30,30 | 2HIDRV.3 29.66,30.34 30,30 | 29.66,29.66 2HIDRV.2 | R36.1 29.66,29.66
N$13  (via drill 1 pad 1.5)
  Top 3: 6,65 v9,65
  Bottom 3: v9,65 6,65
N$14
  Top 0.5: R20.2 27.1,59.25 D19.1
N$15
  Top 0.5: R39.1 75.9,29.55 R40.2
N$16
  Top 0.5: 30,44 30,44.2 | 30,44.2 29.9,43.97 | 2LODRV.2 30.33,43.67 30,44 | 30,44.2 30,44 | 2LODRV.3 30.33,44.53 30,44.2 | R35.1 30,44 | 30,44 36,44 37.45,45.45 FAST.1
N$17
  Top 0.5: R25.2 R26.2 37.1,20.8 38.4,20.8 39.2,20 VREG.1
N$18
  Top 0.5: Q10.E 34.8,63.25 40.6,63.25 D20.3 D21.3
N$19
  Top 0.5: D11.A 88,19 87,20 86,20 85,21 79,21.09 | C5.1 79,21.09 | R40.1 79.55,24.15 D23.A 79.4,21.48 79,21.09
N$20
  Top 0.5: D1.C 22.3,32.9 D5.K
N$21
  Top 0.5: R12.S 78.85,11 Q6.1 79,9.05 C12.2
N$23
  Top 0.5: R9.2 R27.1
N$24
  Top 0.5: D6.C 24.7,82.9 D7.K
N$25
  Top 0.5: Q10.B 31.95,61.05 R19.1
N$26
  Top 0.5: R23.2 29,60.9 Q10.C
N$29
  Top 0.5: R28.1 86,15 85,16 84.4,16 R29.2 R10.2 82,15.6 R12.E
N$30
  Top 0.5: R12.A 84.46,8.46 86,10 R28.2 D11.K D12.K
O_IFB  (via drill 0.6 pad 1.5)
  Top 0.5: v42,53 39.63,54.37 FUSE.6 FUSE.3 29.27,54.37 R24.2 R23.1 D19.3 C17.1 26,54 R46.2 | v72,16 72,13.32 JP7.1
  Bottom 0.5: v42,53 63,53 64,52 64,24 v72,16
PUMP+  (via drill 0.6)  (1 unrouted)
  Top 0.406: P+2.1 P+1.1
  Top 0.5: P+1.1 88,75 89,76 89,83 88.65,84.35 R11.1 84.4,85.35 TRAFO.3 | P+2.1 85,73 85.38,73.27 | C4.+ 42.46,114 | Q4.D M4.D 6,77.5 8,77.5 | M3.D 6.9,16 7,16.1 | C20.1 14.96,90.46 15.5,91 | v18,13 18,10 18.73,8.27 VENT.2
  Top 3: 15.5,91 15.5,88 | 6,77.5 8,77.5 | 5.9,16.1 7,16.1 8.9,16.1 | 14.5,63 15.5,63
  Bottom 0.5: C1.+ 84,106 84,101 91,101 92,100 92,74 90,72 P+2.1 | 14,78 14,88 13.46,88.54 C20.1 | 14,78 9,78 | 11,77.5 14,77.5 | M4.D 11,77.5 | 11,77.5 14,78 | M3.D 16,16 | 16,16 17,16 17,54 16.54,54.46 C19.1 | 16,16 v18,13
  pour Top (isolate 2, rank 2): 89,86 89,73 85,73 85,77 88,77 88,84.6 84,84.6 84,86
  pour Bottom (isolate 2, rank 2): 38,121 92,121 92,108 83,108 79,112 66,112 63,109 63,108 60,108 60,110 58,112 45,112 44,111 44,108 18,108 17,107 17,84 13,84 13,99 14.5,100 14.5,109 17.5,112 37,112 38,113
  pour Top (isolate 2, rank 4): 40,121 92,121 92,108 83,108 79,112 66,112 63,109 63,108 60,108 60,110 58,112 45,112 44,111 44,108 17,108 16,107 11,109 14,112 37,112 38,113
  pour Bottom (isolate 2, rank 4): 3,18 13,18 13,74 12,76 9,76 7,78 9,80 12,80 13,81 13,90 14,91 15,91 18,88 20,52 20,16 17,13 4,13 3,14
RED  (via drill 0.6 pad 1.5, 2.3 pad 1.5)  (2 unrouted)
  Top 0.5: VS2.2 v54,26 | R31.1 11.45,23.55 v9,26 | Q1.D M1.D 6,46.5
  Top 3: 6,46.5 8,46.5 | 6,60 8,60
  Route2 0.5: v54,26 53,25
  other vias: 6,30
  pour Top (isolate 2): 4,21 4,35 12,35 12,24 13,24 11,22 9,22 8,21
  pour Bottom (isolate 2): 4.5,61.5 10,61.5 11,55 11,50 14,48 14,20 4,20 4,35 10,41 5,48 9,48 9,54 4.55,56
SCR2
  pour Top (isolate 2): 89,64 89,61 75,61 75,64
  pour Bottom (isolate 2): 89,64 89,61 75,61 75,64
SD  (via drill 0.6 pad 1.5)
  Top 0.5: FAST.13 48.37,41.63 47.5,42 47.5,55 47,55 | 47,55 43.27,55 42.27,55.73 v42,56 41.37,55.63 FUSE.7 | SLOW.13 57.37,80.64 60,78 v60,55 | R37.1 48,54 47,55
  Bottom 0.5: v42,56 44,56 45,55 v60,55
SNUB1
  pour Top (isolate 2, rank 3): 73,64 73,52 66,52 66,64
  pour Bottom (isolate 2, rank 3): 73,64 73,52 66,52 66,64
SNUB2
  pour Top (isolate 2, rank 3): 73,48 73,36 66,36 66,48
  pour Bottom (isolate 2, rank 3): 73,48 73,36 66,36 66,48
SOURCE
  pour Top (isolate 2): 89,48 89,45 75,45 75,48
  pour Bottom (isolate 2): 89,48 89,45 75,45 75,48
TFB  (via drill 0.6 pad 1.5)
  Top 0.5: C2.1 34,13.22 JP7.16 34.2,10.78 v34.3,10.5 | NTC.1 32.63,7.63 v32.6,8.1
  Route2 0.5: 31.68,4.95 NTC.1
  Bottom 0.5: v32.6,8.1 32.6,9.6 v34.3,10.5
V12  (via drill 0.6 pad 1.5)
  Top 0.5: C7.+ 82.45,77.45 81,76 78,76 V12_1.1 | V12_1.1 R13.2 | D9.K 74,78 V12_1.1 | 31,41 33,41 C16.1 35.55,42.45 v36.7,41.9 36.6,41.8 37.2,42.9 39.7,42.91 FAST.3 | 31,41 24,41 | 24,41 23.7,41 | FUSE.8 37.7,57.7 v37,59 37.1,59.6 R21.2 | v44.4,10.5 44.3,12.92 JP7.12 | JP7.12 44.2,13.18 | JP7.12 44.34,13.04 VREG1.3 44.3,16.14 44.3,16.8 44,17.1 44,18 | 2LODRV.8 23.67,41.33 24,41 | 2LODRV.1 30.33,41.67 31,41 | 1LODRV.8 24.3,96.89 24.46,96.73 24.46,95.88 27.29,93.05 28,92.34 28.47,92.34 1LODRV.1 30,91.89 30,91 31.5,89.5 | VREG.3 43.8,18.2 44,18 | C8.+ 44.1,17.9 44,18 | SLOW.3 39.09,81.91 v37,84 | v37,84 31.5,89.5 | C15.1 32.1,90.1 31.5,89.5 | D10.A 34.4,68.6 v37,67.5 37.45,69 C14.1 | v37,84 36,83 v37,84 | D8.A 43.53,32.07 R38.2 46,33 C13.1
  Top 1: v69,68.5 69.5,69 77,69 V12_2.1 V12_1.1
  Bottom 0.5: v37,67.5 v37,59 37,42 | v37,67.5 39,70 39,82 v37,84 | v36.7,41.9 37,42 | v37,67.5 39.8,67.5 40.9,68.6 v69,68.5 | v44.4,10.5 44.3,16.8 44.1,17 42,20 36,20 36,27 40,31 44,31 44,34 | v36.7,41.9 36.1,42 37,42 | v36.7,41.9 42.9,41.9 44,40 44,34 | 44,34 R38.2
  pour Top (isolate 2): 83,79 83,73 74,73 74,78 81,78
  pour Top (isolate 1): 23,98 23,96 36,83 37,83 38,84 24,98
  pour Top (isolate 1.5): 35,69 39,69 39,67 35,67
  pour Top (isolate 1.5): 22,42 37,42 37,40.5 22,40.5
VB1
  Top 0.5: SLOW.7 43.17,76.83 44,76 44,74 43,72.5 37.5,72.5 C21.1 37.24,71.89 37.24,71.24 37,71 36.49,71.51 34.21,71.51 | D10.K 29.6,69.6 30,70 | 1HIDRV.8 25.67,70.33 26,70 30,70 | 30,70 31,71 31.23,71 1HIDRV.1
  pour Top (isolate 1.5, rank 2): 24,72 37,72 37,71 33,71 31,67 24,67
VB2
  Top 0.5: 33.18,29 34,29 35,30 | 35,30 36,31 35.99,31.01 36,31.02 36,32 39,35 43.5,35 43.5,37.5 43.2,37.8 42.83,37.83 FAST.7 | 35,30 36.4,31 D8.K 38.5,32.5 | 2HIDRV.1 31.45,28.55 32,28 | 2HIDRV.8 26.95,24.05 28,23
  pour Top (isolate 1.5): 27,23 28,22 37,31 37,33 36,33 27,24
VDD  (via drill 0.6, 0.6 pad 1.5)
  Top 0.5: 41.9,23.1 R26.1 | 41.9,23.1 42,23 42,21.6 41.6,21.2 41.6,19 40.4,17.8 39.5,17.8 39.26,17.56 VREG1.1 39.3,16.06 JP7.14 39.3,11.3 v39.4,10.5 | VREG.4 41.5,23.5 41.9,23.1 | v35.2,8 35,6.07 NTC.2 | v45.5,22.7 C6.+ | v82,5 81.9,4.9 C12.1 77.2,4.9 R47.2
  Bottom 0.5: v39.4,10.5 39.4,10.6 v35.2,8 | R18.1 50.5,29.5 49,28 49,25.88 46.03,22.91 45.71,22.91 v45.5,22.7 | v82,5 81,4.5 36,4.5 35,5 35,5.73 NTC.2
  pour Top (isolate 0.8): 39,25 47,25 47,24 45,20 43,20 43,19 40,15 37,15 37,23
VDD1  (via drill 0.6)
  Top 0.5: SLOW.11 53.91,78.09 55,77 v55,49 | FAST.11 50.2,39 51,39 52,39 53.6,39 53.6,35.4 53.4,35.4 52,34 R38.1
  Bottom 0.5: v55,49 55,38 52,35 51,34 R38.1 50.54,32.79 R18.2
VFB
  Top 0.5: JP7.15 36.76,9.84 36.76,9.24 41,4.5 42,4.5 | Q6.3 76.1,7 75,7 73.9,5.9 R47.1 72.4,4.5 42,4.5 | C10.1 42.2,4.7 42,4.5
VS3
  Top 0.5: ROUT6.1 19.25,28.1 | 19.25,28.1 19.3,28.51 | 2HIDRV.4 28.55,31.45 28,32 | FAST.6 36.09,39.09 33,36 32.81,35 C22.2 | 2HIDRV.5 24.05,26.95 23,28 | 23,28 23.9,28 | 23,28 19.35,28 19.25,28.1
  pour Top (isolate 1.5, rank 2): 18,31 23,31 24,30 25,30 35,40 36,38 25,27 22,26 18,28
VS4
  Top 0.5: ROUT8.1 D6.A | SLOW.6 38.09,78.09 38,78 36,76 36.05,76 C21.2 36.5,76.5 36,77 32,77 | 1HIDRV.5 25.67,76.67 26,77 32,77 | 32,77 32,76.23 1HIDRV.4 32.33,76.67 32,77
  pour Top (isolate 1.5): 20,83 23,83 23,79 24,78 38,78 38,76 20,76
